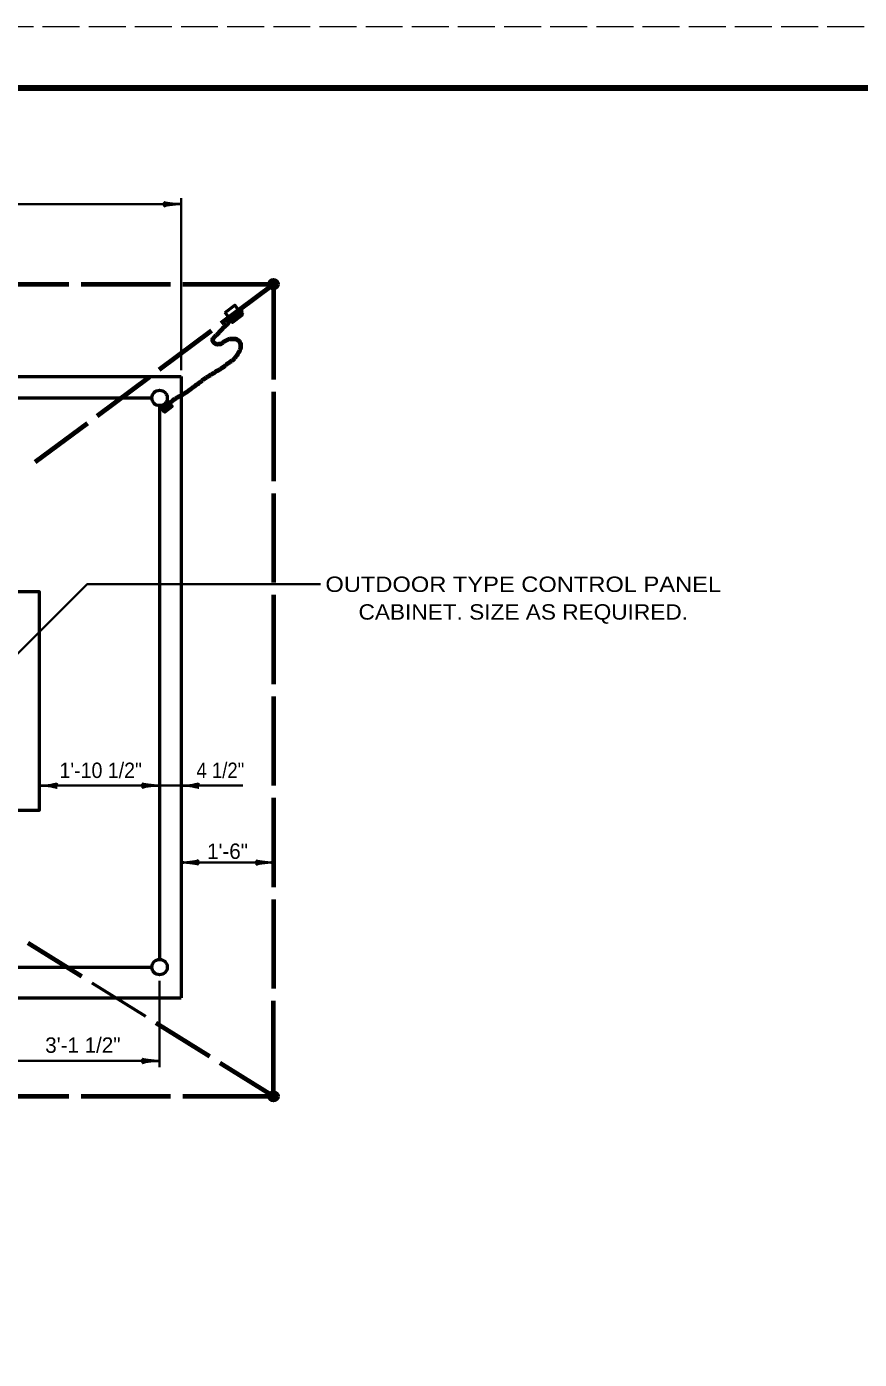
# Model space of a CAD drawing. Extents: x -1 to 679, y 0 to 440.
# Drawn here: x 236 to 371.3, y 223.4 to 440 of the extents above; entities that cross this region are included whole.
import ezdxf
from ezdxf.enums import TextEntityAlignment as Align

# ---------------------------------------------------------------- set-up
doc = ezdxf.new("R2010")
doc.units = 0
doc.linetypes.add('LONG_DASHED', pattern=[7.5, 6, -1.5])
doc.layers.add('1', color=7, linetype='Continuous', lineweight=53)
doc.layers.add('61', color=7, linetype='Continuous', lineweight=35)

msp = doc.modelspace()

# ---------------------------------------------------------------- hatches: boundary and pattern name
at = {"layer": '1'}
for points in [[(276.832, 398.11, 1), (275.332, 398.11, 1)], [(276.832, 266.11, 1), (275.332, 266.11, 1)]]:
    msp.add_hatch(color=256, dxfattribs=at).paths.add_polyline_path(points)

# ---------------------------------------------------------------- linework, layer by layer
at = {"layer": '1', "lineweight": 35}
for p, q in [((261.082, 384.11), (261.082, 412.11)), ((111.082, 411.11), (261.082, 411.11)), ((261.082, 304.11), (276.082, 304.11)), ((257.582, 284.86), (257.582, 270.86))]:
    msp.add_line(p, q, dxfattribs=at)
at = {"layer": '1', "lineweight": 70}
for p, q in [((228.332, 398.11), (242.832, 398.11)), ((244.832, 398.11), (259.332, 398.11)), ((261.332, 398.11), (276.082, 398.11)), ((267.609, 391.782), (276.082, 398.11)), ((276.082, 398.11), (276.082, 382.61)), ((257.534, 384.258), (266.007, 390.586)), ((247.459, 376.733), (255.932, 383.061)), ((276.082, 380.61), (276.082, 366.11)), ((237.383, 369.209), (245.856, 375.536)), ((276.082, 364.11), (276.082, 349.61)), ((276.082, 347.61), (276.082, 333.11)), ((276.082, 331.11), (276.082, 316.61)), ((276.082, 314.61), (276.082, 300.11)), ((276.082, 298.11), (276.082, 283.61)), ((236.18, 291.08), (244.884, 285.633)), ((276.082, 266.11), (276.082, 281.61)), ((256.979, 278.064), (265.683, 272.618)), ((267.378, 271.557), (276.082, 266.11)), ((228.332, 266.11), (242.832, 266.11)), ((244.832, 266.11), (259.332, 266.11)), ((261.332, 266.11), (276.082, 266.11))]:
    msp.add_line(p, q, dxfattribs=at)
at = {"layer": '1'}
for p, q in [((111.082, 383.11), (261.082, 383.11)), ((261.082, 383.11), (261.082, 282.11)), ((115.832, 379.61), (256.332, 379.61)), ((257.582, 378.36), (257.582, 288.36)), ((234.332, 287.11), (256.332, 287.11)), ((246.579, 284.572), (255.283, 279.125)), ((111.082, 282.11), (261.082, 282.11))]:
    msp.add_line(p, q, dxfattribs=at)
for points in [[(268.213, 393.481), (269.815, 394.678), (271.012, 393.075), (269.41, 391.879)], [(257.821, 378.127), (259.023, 379.025), (259.621, 378.224), (258.419, 377.326), (257.821, 378.127)]]:
    msp.add_lwpolyline(points, close=True, dxfattribs=at)
at = {"layer": '1', "lineweight": 35}
for points in [[(233.082, 336.61), (245.81, 349.338), (283.703, 349.338)], [(238.082, 316.61), (257.582, 316.61), (261.082, 316.61), (271.082, 316.61)], [(114.582, 271.86), (140.832, 271.86), (200.635, 271.86), (231.332, 271.86), (257.582, 271.86)]]:
    msp.add_lwpolyline(points, dxfattribs=at)
at = {"layer": '1'}
msp.add_lwpolyline([(186.582, 312.61), (238.082, 312.61), (238.082, 348.11), (186.582, 348.11)], dxfattribs=at)
for centre, radius in [((276.082, 398.11), 0.75), ((257.582, 379.61), 1.25), ((257.582, 287.11), 1.25), ((276.082, 266.11), 0.75)]:
    msp.add_circle(centre, radius, dxfattribs=at)
at = {"layer": '1', "lineweight": 40}
for centre, major_axis, ratio, start_param, end_param in [((259.991, 410.834), (1.786, 0.156), 0.122415, 0.8963533, 3.1415927), ((259.962, 411.322), (-1.756, 0.176), 0.07063, 6.2823074, 8.5597026), ((239.203, 316.399), (-1.756, 0.176), 0.07063, 3.1407148, 5.41811), ((239.174, 316.887), (-1.786, -0.156), 0.122415, 0.8963533, 3.1415927), ((256.491, 316.334), (1.786, 0.156), 0.122415, 0.8963533, 3.1415927), ((256.491, 316.334), (1.786, 0.156), 0.122415, 0.8963533, 3.1415927), ((256.462, 316.822), (1.756, -0.176), 0.07063, 3.1407148, 5.41811), ((256.462, 316.822), (1.756, -0.176), 0.07063, 3.1407148, 5.41811), ((262.203, 316.399), (-1.756, 0.176), 0.07063, 3.1407148, 5.41811), ((262.174, 316.887), (-1.786, -0.156), 0.122415, 0.8963533, 3.1415927), ((262.203, 303.899), (-1.756, 0.176), 0.07063, 3.1407148, 5.41811), ((262.174, 304.387), (-1.786, -0.156), 0.122415, 0.8963533, 3.1415927), ((274.991, 303.834), (1.786, 0.156), 0.122415, 0.8963533, 3.1415927), ((274.962, 304.322), (1.756, -0.176), 0.07063, 3.1407148, 5.41811), ((256.491, 271.584), (1.786, 0.156), 0.122415, 0.8963533, 3.1415927), ((256.462, 272.072), (1.756, -0.176), 0.07063, 3.1407148, 5.41811)]:
    msp.add_ellipse(centre, major_axis=major_axis, ratio=ratio, start_param=start_param, end_param=end_param, dxfattribs=at)
at = {"layer": '1', "lineweight": 70}
for points in [[(268.438, 388.958), (268.229, 388.854), (268.047, 388.75), (267.89, 388.645), (267.76, 388.515), (267.578, 388.411), (267.369, 388.359), (267.161, 388.333), (266.926, 388.333), (266.666, 388.411), (266.483, 388.541), (266.353, 388.698), (266.249, 388.854), (266.249, 389.115), (266.405, 389.401), (266.562, 389.584), (266.666, 389.714), (266.874, 389.871), (266.978, 390.001), (267.187, 390.183), (267.317, 390.366), (267.5, 390.548), (267.682, 390.731), (267.838, 390.887), (268.021, 391.096), (268.203, 391.252), (268.333, 391.382), (268.542, 391.565), (268.698, 391.721), (268.854, 391.93), (268.959, 392.086), (269.063, 392.216), (269.245, 392.425), (269.428, 392.555), (269.662, 392.66), (269.844, 392.764), (270.079, 392.946), (270.287, 393.129), (270.548, 393.233), (270.782, 393.311), (270.965, 393.416), (271.121, 393.546), (271.173, 393.572)], [(267.813, 384.534), (267.921, 384.62), (268.13, 384.777), (268.286, 384.907), (268.442, 385.038), (268.625, 385.194), (268.833, 385.35), (268.989, 385.455), (269.172, 385.585), (269.432, 385.741), (269.589, 385.846), (269.693, 385.976), (269.797, 386.106), (269.953, 386.289), (270.084, 386.445), (270.188, 386.575), (270.37, 386.862), (270.474, 387.071), (270.605, 387.279), (270.683, 387.462), (270.761, 387.696), (270.787, 387.931), (270.787, 388.139), (270.761, 388.374), (270.657, 388.635), (270.474, 388.895), (270.266, 389.026), (270.11, 389.13), (269.875, 389.156), (269.562, 389.182), (269.198, 389.182), (268.963, 389.156)], [(268.963, 389.156), (268.729, 389.104), (268.572, 389.026), (268.364, 388.921), (268.287, 388.873)], [(257.886, 377.594), (258.12, 377.698), (258.329, 377.802), (258.485, 377.906), (258.615, 378.037), (258.798, 378.219), (258.954, 378.376), (259.058, 378.506), (259.188, 378.688), (259.345, 378.871), (259.527, 379.053), (259.709, 379.184), (259.866, 379.34), (260.126, 379.47), (260.257, 379.575), (260.413, 379.679), (260.569, 379.757), (260.83, 379.913), (261.116, 380.044), (261.377, 380.2), (261.559, 380.33), (261.82, 380.487), (262.132, 380.669), (262.393, 380.878), (262.706, 381.113), (262.966, 381.295), (263.096, 381.399), (263.253, 381.503), (263.461, 381.686), (263.591, 381.79), (263.774, 381.868), (263.982, 382.051), (264.139, 382.155), (264.321, 382.285), (264.451, 382.39), (264.608, 382.546), (264.764, 382.65), (264.998, 382.807), (265.155, 382.911), (265.337, 383.067), (265.546, 383.172), (265.754, 383.302), (266.014, 383.458), (266.223, 383.589), (266.457, 383.719), (266.64, 383.875), (266.874, 384.006), (267.135, 384.136), (267.317, 384.24), (267.5, 384.345), (267.708, 384.501), (267.89, 384.605), (268.047, 384.71), (268.119, 384.758)]]:
    msp.add_spline(points, degree=3, dxfattribs=at)
at = {"layer": '61', "linetype": 'LONG_DASHED', "lineweight": 13}
msp.add_line((-1.431, 439.961), (678.589, 439.961), dxfattribs=at)
at = {"layer": '61', "lineweight": 158}
msp.add_lwpolyline([(667.609, 429.961), (28.569, 429.961), (28.569, 9.941)], dxfattribs=at)

# ---------------------------------------------------------------- texts
at = {"layer": '1'}
for s, width, p in [('OUTDOOR TYPE CONTROL PANEL', 1.15, (316.674, 348.084)), ('CABINET. SIZE AS REQUIRED.', 1.1, (316.674, 343.584))]:
    msp.add_text(s, height=2.5, dxfattribs=dict(at, width=width)).set_placement(p, align=Align.CENTER)
for s, width, p in [('1\'-10 1/2"', 0.95, (241.326, 317.846)), ('4 1/2"', 0.9, (263.576, 317.846))]:
    msp.add_text(s, height=2.5, dxfattribs=dict(at, width=width)).set_placement(p)
for s, p in [('1\'-6"', (265.296, 304.694)), ('3\'-1 1/2"', (239.003, 273.183))]:
    msp.add_text(s, height=2.5, dxfattribs=at).set_placement(p)

doc.saveas('drawing.dxf')
